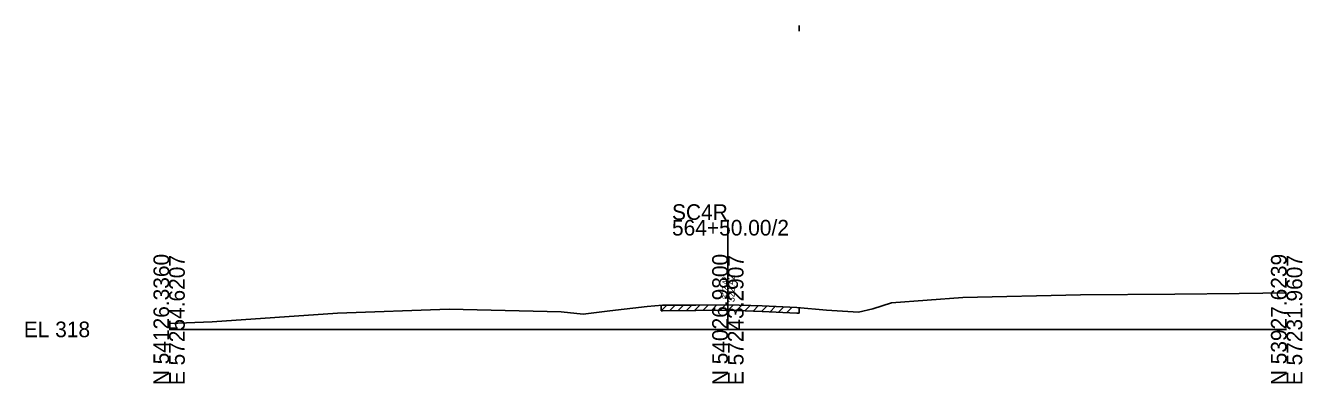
# Model space of a CAD drawing. Extents: x 8330 to 11559, y 6854 to 26418.
# Drawn here: x 11330.1 to 11558.7, y 23354.5 to 23418.6 of the extents above; entities that cross this region are included whole.
import ezdxf

# ---------------------------------------------------------------- set-up
doc = ezdxf.new("R2010")
doc.units = 0
for name, color, linetype in [('Level 10', 7, 'Continuous'), ('Level 59', 7, 'Continuous'), ('Level 60', 7, 'Continuous'), ('Level 61', 7, 'Continuous'), ('Level 63', 7, 'Continuous')]:
    doc.layers.add(name, color=color, linetype=linetype)

msp = doc.modelspace()

# ---------------------------------------------------------------- linework, layer by layer
at = {"layer": 'Level 60'}
for p, q in [((11485.09, 23368.94), (11497.91, 23369.87)), ((11497.91, 23369.87), (11518.95, 23370.37)), ((11518.95, 23370.37), (11535.83, 23370.5)), ((11535.83, 23370.5), (11547.34, 23370.62)), ((11547.34, 23370.62), (11555.83, 23370.71)), ((11385.99, 23367.06), (11405.93, 23367.8)), ((11405.93, 23367.8), (11426, 23367.3)), ((11434.71, 23367.52), (11441.38, 23368.29)), ((11441.38, 23368.29), (11444.14, 23368.5)), ((11444.14, 23368.5), (11450.07, 23368.53)), ((11450.07, 23368.53), (11455.83, 23368.59)), ((11455.83, 23368.59), (11461.94, 23368.4)), ((11461.94, 23368.4), (11468.18, 23368.09)), ((11468.18, 23368.09), (11473.48, 23367.62)), ((11473.48, 23367.62), (11479.21, 23367.24)), ((11479.21, 23367.24), (11481.79, 23367.87)), ((11481.79, 23367.87), (11485.09, 23368.94)), ((11355.83, 23365.25), (11363.56, 23365.51)), ((11363.56, 23365.51), (11385.99, 23367.06)), ((11426, 23367.3), (11429.95, 23366.91)), ((11429.95, 23366.91), (11434.71, 23367.52))]:
    msp.add_line(p, q, dxfattribs=at)
at = {"layer": 'Level 61'}
for p, q in [((11468.61, 23417.59), (11468.61, 23418.59)), ((11468.61, 23417.59), (11468.61, 23418.59)), ((11444.89, 23368.51), (11443.87, 23367.48)), ((11443.87, 23368.48), (11443.87, 23367.48)), ((11446.37, 23368.51), (11445.37, 23367.51)), ((11447.87, 23368.52), (11446.87, 23367.52)), ((11449.37, 23368.53), (11448.37, 23367.52)), ((11450.88, 23368.54), (11449.87, 23367.53)), ((11450.07, 23367.53), (11455.83, 23367.59)), ((11452.38, 23368.55), (11451.37, 23367.54)), ((11453.88, 23368.57), (11452.87, 23367.56)), ((11455.38, 23368.59), (11454.37, 23367.58)), ((11455.83, 23367.59), (11461.94, 23367.4)), ((11456.83, 23368.56), (11455.87, 23367.59)), ((11458.33, 23368.51), (11457.37, 23367.54)), ((11459.83, 23368.46), (11458.87, 23367.5)), ((11461.33, 23368.42), (11460.37, 23367.45)), ((11462.82, 23368.35), (11461.87, 23367.4)), ((11464.32, 23368.28), (11463.37, 23367.33)), ((11465.82, 23368.21), (11464.87, 23367.25)), ((11467.32, 23368.13), (11466.37, 23367.18)), ((11468.61, 23367.05), (11468.61, 23368.05)), ((11443.87, 23367.48), (11444.14, 23367.5)), ((11444.14, 23367.5), (11450.07, 23367.53)), ((11461.94, 23367.4), (11468.18, 23367.09)), ((11468.18, 23367.09), (11468.61, 23367.05))]:
    msp.add_line(p, q, dxfattribs=at)
at = {"layer": 'Level 63'}
for p, q in [((11455.83, 23364.17), (11455.83, 23383.78)), ((11355.83, 23364.17), (11455.83, 23364.17)), ((11455.83, 23364.17), (11555.83, 23364.17))]:
    msp.add_line(p, q, dxfattribs=at)

# ---------------------------------------------------------------- texts
at = {"layer": 'Level 10'}
msp.add_text('322.42', height=1, rotation=90, dxfattribs=at).set_placement((11455.83, 23369.59))
at = {"layer": 'Level 59'}
msp.add_text(' 322.42', height=1.2, rotation=90, dxfattribs=at).set_placement((11457.03, 23368.59))
msp.add_text(' 322.42', height=1.2, rotation=90, dxfattribs=at).set_placement((11457.03, 23368.59))
msp.add_text(' 322.42', height=1.2, rotation=90, dxfattribs=at).set_placement((11457.03, 23368.59))
at = {"layer": 'Level 63'}
for s, p in [('SC4R', (11445.83, 23383.78)), ('564+50.00/2', (11445.83, 23380.98)), ('EL 318', (11329.82, 23362.77))]:
    msp.add_text(s, height=2.8, dxfattribs=at).set_placement(p)
for s, p in [('N 54126.3360', (11355.83, 23354.17)), ('E 57254.6207', (11358.63, 23354.17)), ('N 54026.9800', (11455.83, 23354.17)), ('E 57243.2907', (11458.63, 23354.17)), ('N 53927.6239', (11555.83, 23354.17)), ('E 57231.9607', (11558.63, 23354.17))]:
    msp.add_text(s, height=2.8, rotation=90, dxfattribs=at).set_placement(p)

doc.saveas('drawing.dxf')
